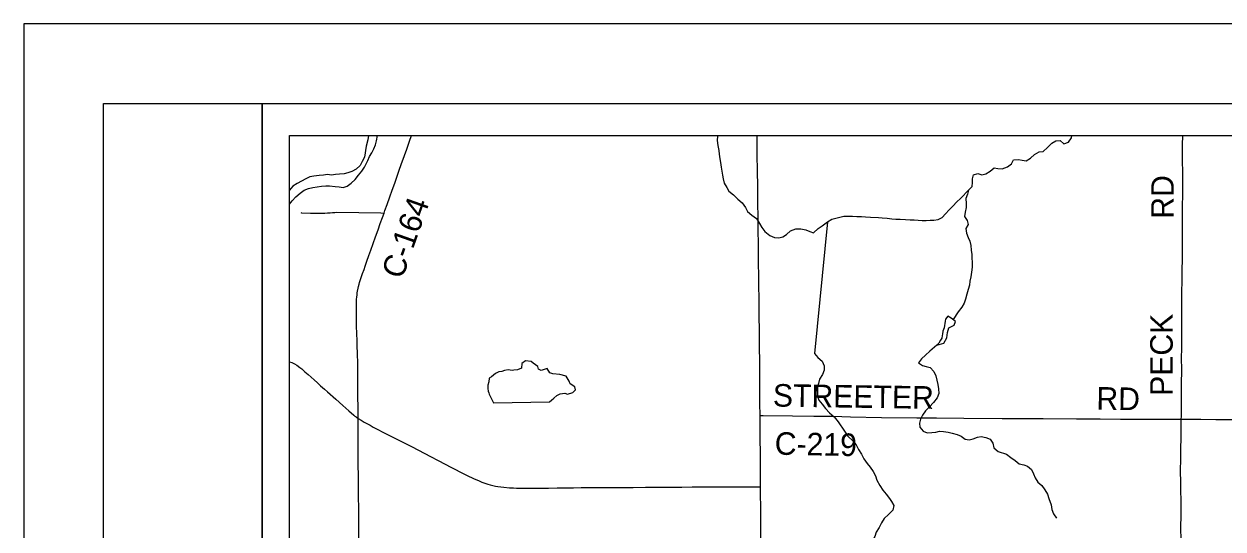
# Model space of a CAD drawing. Extents: x 0 to 34, y 0 to 22.
# Drawn here: x 0 to 7.55, y 18.82 to 22 of the extents above; entities that cross this region are included whole.
import ezdxf

# ---------------------------------------------------------------- set-up
doc = ezdxf.new("R2010")
doc.units = 0
for name, color, linetype in [('GM_X_County_Road', 7, 'Continuous'), ('GM_X_County_Road_Text', 7, 'Continuous'), ('GM_X_Major_River', 7, 'Continuous'), ('GM_X_Minor_Lake', 7, 'Continuous'), ('GM_X_Minor_River', 7, 'Continuous'), ('GM_X_State_Route', 7, 'Continuous'), ('GM_X_Township_Road', 7, 'Continuous'), ('SH_Border', 7, 'Continuous'), ('SH_Cut_Line', 7, 'Continuous'), ('SH_Text', 7, 'Continuous')]:
    doc.layers.add(name, color=color, linetype=linetype)

msp = doc.modelspace()

# ---------------------------------------------------------------- linework, layer by layer
at = {"layer": 'GM_X_County_Road'}
for points in [[(2.2666, 20.8105), (2.2724, 20.8264), (2.2858, 20.8633), (2.3041, 20.9132), (2.3186, 20.9539), (2.3343, 20.9988), (2.3522, 21.0497), (2.3601, 21.0731), (2.3771, 21.122), (2.3869, 21.1504), (2.3946, 21.1718), (2.4095, 21.2132), (2.427, 21.2637), (2.4389, 21.2991)], [(7.286, 19.5135), (7.2862, 19.5297), (7.2864, 19.6137), (7.2873, 19.7224), (7.2888, 19.8343), (7.2879, 19.8886), (7.2887, 19.9679), (7.2894, 20.0347), (7.2899, 20.0999), (7.2903, 20.145), (7.2894, 20.191), (7.2887, 20.2313), (7.2896, 20.3121), (7.2908, 20.3835), (7.2914, 20.427), (7.2921, 20.4517), (7.2923, 20.4641), (7.293, 20.5067), (7.2929, 20.5944), (7.2929, 20.619), (7.2932, 20.6546), (7.2933, 20.7079), (7.2933, 20.7508), (7.2942, 20.8094), (7.2942, 20.8523), (7.2946, 20.9271), (7.2955, 20.9978), (7.2959, 21.0576), (7.2942, 21.1503), (7.2944, 21.1921), (7.2935, 21.2264), (7.294, 21.2523), (7.2947, 21.2833), (7.2954, 21.2991)], [(2.1033, 19.5185), (2.1031, 19.567), (2.1029, 19.5985), (2.1027, 19.6438), (2.1024, 19.7134), (2.1023, 19.7491), (2.1022, 19.7835), (2.1019, 19.818), (2.1016, 19.8431), (2.1012, 19.8755), (2.1003, 19.9139), (2.0995, 19.936), (2.0984, 19.9665), (2.0973, 20.0038), (2.0957, 20.0539), (2.0943, 20.0976), (2.0936, 20.13), (2.093, 20.1663), (2.0927, 20.1819), (2.0928, 20.1999), (2.0929, 20.2245), (2.0933, 20.2419), (2.0938, 20.2566), (2.0944, 20.2686), (2.0956, 20.2822), (2.097, 20.2948), (2.0986, 20.3074), (2.1007, 20.3196), (2.1041, 20.3369), (2.1069, 20.349), (2.1104, 20.3624), (2.1131, 20.3727), (2.1168, 20.3854), (2.121, 20.398), (2.1253, 20.4113), (2.1317, 20.4296), (2.1408, 20.4557), (2.1482, 20.4769), (2.1588, 20.5071), (2.1715, 20.5435), (2.1835, 20.5772), (2.1983, 20.619), (2.2129, 20.6602), (2.2289, 20.7051), (2.2429, 20.7445), (2.2561, 20.7815), (2.2666, 20.8105)], [(2.1088, 18.767), (2.1076, 18.9038), (2.1071, 18.9571), (2.1065, 19.0215), (2.106, 19.0762), (2.1055, 19.1442), (2.1048, 19.2394), (2.1044, 19.3044), (2.1039, 19.3805), (2.1036, 19.4313), (2.1033, 19.5185)], [(4.6341, 19.5365), (4.6542, 19.5363), (4.8374, 19.5343), (4.9723, 19.5333), (5.0953, 19.5316), (5.2034, 19.5274), (5.3978, 19.5241), (5.6207, 19.5222), (5.7446, 19.522), (5.9176, 19.5198), (6.1577, 19.5182), (6.2756, 19.5175), (6.417, 19.5176), (6.6267, 19.5162), (6.7758, 19.5153), (6.9032, 19.5141), (7.1346, 19.5131), (7.286, 19.5135)], [(7.285, 18.7426), (7.284, 18.8433), (7.2844, 18.8984), (7.2841, 18.9654), (7.2824, 19.1009), (7.2818, 19.2024), (7.2826, 19.2499), (7.2836, 19.3184), (7.2848, 19.4039), (7.286, 19.5135)], [(7.286, 19.5135), (7.3057, 19.5134), (7.4098, 19.5125), (7.5034, 19.5116), (7.6091, 19.5105)]]:
    msp.add_lwpolyline(points, dxfattribs=at)
at = {"layer": 'GM_X_Major_River'}
for points in [[(2.1683, 21.2991), (2.1649, 21.271), (2.1534, 21.2314), (2.1432, 21.1623)], [(2.1444, 21.0987), (2.1652, 21.1412), (2.1755, 21.1659), (2.1906, 21.1898), (2.2018, 21.2155), (2.2131, 21.2393), (2.2196, 21.265), (2.2252, 21.2983), (2.2254, 21.2991)], [(2.1432, 21.1623), (2.1281, 21.1357), (2.1159, 21.11), (2.0923, 21.0862), (2.0649, 21.0727), (2.0394, 21.0631), (2.0148, 21.0573), (1.9873, 21.0543), (1.9617, 21.0523), (1.9361, 21.0493), (1.9115, 21.052), (1.8859, 21.0491), (1.8594, 21.0461), (1.8243, 21.0431), (1.7997, 21.0392), (1.7742, 21.0257), (1.7468, 21.0104), (1.7194, 20.9961), (1.6929, 20.9789), (1.6712, 20.9541), (1.6712, 20.9541)], [(1.9241, 20.981), (1.9583, 20.9773), (1.9848, 20.9756), (2.0104, 20.9719), (2.035, 20.9796), (2.0605, 20.9987), (2.086, 21.0207), (2.1067, 21.0483), (2.1265, 21.073), (2.1444, 21.0987)], [(1.6712, 20.8658), (1.6886, 20.8878), (1.7122, 20.9135), (1.7386, 20.9364), (1.7632, 20.9536), (1.7906, 20.9642), (1.8181, 20.9709), (1.8465, 20.9758), (1.872, 20.9788), (1.8995, 20.9808), (1.9241, 20.981)]]:
    msp.add_lwpolyline(points, dxfattribs=at)
at = {"layer": 'GM_X_Minor_Lake'}
for p, q in [((5.8, 20.1304), (5.7926, 20.0885)), ((2.9291, 19.6702), (2.9568, 19.6162))]:
    msp.add_line(p, q, dxfattribs=at)
for points in [[(5.7926, 20.0885), (5.7851, 20.0676), (5.7833, 20.0486), (5.7815, 20.0391), (5.7787, 20.0229), (5.7693, 20.0096), (5.7599, 19.9924), (5.7461, 19.9796), (5.7912, 19.9907), (5.8109, 20.0259), (5.8146, 20.0583), (5.823, 20.0887), (5.8561, 20.106), (5.8636, 20.1288), (5.8369, 20.1496), (5.817, 20.1618), (5.8019, 20.1437), (5.8, 20.1304)], [(2.9568, 19.6162), (3.3079, 19.6217), (3.3201, 19.6332), (3.3362, 19.6466), (3.3551, 19.6628), (3.375, 19.6734), (3.4053, 19.6774), (3.4224, 19.6708), (3.4556, 19.6814), (3.4726, 19.6976), (3.4687, 19.7176), (3.4383, 19.7355), (3.4325, 19.7526), (3.4124, 19.7838), (3.3735, 19.795), (3.3298, 19.7986), (3.3108, 19.8052), (3.2936, 19.8317), (3.2567, 19.8191), (3.2396, 19.8276), (3.2347, 19.8447), (3.2062, 19.8664), (3.1938, 19.8758), (3.1577, 19.8804), (3.135, 19.8641), (3.1332, 19.8347), (3.1067, 19.8231), (3.0849, 19.8221), (3.0726, 19.8201), (3.0489, 19.8238), (3.0261, 19.8199), (3.0081, 19.8141), (2.9891, 19.8121), (2.9693, 19.8015), (2.9428, 19.7805), (2.9295, 19.7719), (2.9258, 19.749), (2.9212, 19.7281), (2.9203, 19.7062), (2.9214, 19.6901), (2.9262, 19.6797), (2.9291, 19.6702)]]:
    msp.add_lwpolyline(points, dxfattribs=at)
at = {"layer": 'GM_X_Minor_River'}
for points in [[(4.3667, 21.2991), (4.3667, 21.2939), (4.3649, 21.2663), (4.3679, 21.2359), (4.3738, 21.2046), (4.3767, 21.1809), (4.3807, 21.1524), (4.3855, 21.1286), (4.3894, 21.0992), (4.3933, 21.0745), (4.3982, 21.0498), (4.4021, 21.0261), (4.4079, 20.9995), (4.4242, 20.972), (4.4376, 20.9474), (4.4671, 20.9257), (4.4938, 20.8983), (4.5224, 20.8737), (4.5424, 20.8444), (4.5558, 20.8197), (4.5825, 20.7961), (4.611, 20.7763), (4.6311, 20.745), (4.6455, 20.7194), (4.6645, 20.6948), (4.695, 20.6693), (4.7245, 20.6571), (4.752, 20.6544), (4.7767, 20.6612), (4.8013, 20.6746), (4.8258, 20.6975), (4.8599, 20.712), (4.8912, 20.7102), (4.9216, 20.7047), (4.9473, 20.6953), (4.9711, 20.6869), (4.9994, 20.7136), (5.0249, 20.7309), (5.059, 20.7548), (5.0855, 20.7711), (5.112, 20.7788), (5.1357, 20.7837), (5.1613, 20.7905), (5.186, 20.7915), (5.2154, 20.7907), (5.2429, 20.789), (5.2723, 20.7882), (5.2979, 20.7864), (5.3302, 20.7837), (5.3796, 20.7821), (5.4033, 20.7803), (5.4346, 20.7785), (5.4631, 20.7749), (5.4878, 20.7722), (5.5153, 20.7714), (5.5495, 20.7696), (5.5798, 20.7679), (5.6036, 20.767), (5.6292, 20.7653), (5.6548, 20.7626), (5.6804, 20.7636), (5.7042, 20.7647), (5.7288, 20.7667), (5.7563, 20.7707), (5.7809, 20.7822), (5.8017, 20.8061), (5.8244, 20.8299), (5.8489, 20.8548), (5.8716, 20.8796), (5.898, 20.9044), (5.9471, 20.9541), (5.9689, 20.978), (5.9706, 21.0017)], [(5.9706, 21.0017), (5.9705, 21.0264), (5.978, 21.0502), (6.0045, 21.0589), (6.0292, 21.0514), (6.0558, 21.0563), (6.0823, 21.0736), (6.1069, 21.0946), (6.1306, 21.09), (6.1581, 21.0892), (6.1913, 21.1017), (6.2178, 21.1208), (6.23, 21.1456), (6.2603, 21.1467), (6.285, 21.143), (6.3088, 21.1384), (6.3362, 21.1566), (6.3608, 21.1795), (6.392, 21.1958), (6.4167, 21.1978), (6.4431, 21.2236), (6.4705, 21.2504), (6.496, 21.2657), (6.5226, 21.2678), (6.5474, 21.247), (6.5758, 21.2566), (6.5937, 21.2843), (6.5977, 21.2991)], [(5.9471, 20.9541), (5.9406, 20.9284), (5.9294, 20.9017), (5.9323, 20.8704), (5.9306, 20.8447), (5.925, 20.8162), (5.9204, 20.7896), (5.9385, 20.763), (5.9443, 20.7393), (5.9302, 20.7126), (5.9332, 20.6832), (5.9447, 20.6576), (5.9543, 20.6339), (5.9611, 20.6054), (5.964, 20.5779), (5.968, 20.5503), (5.9681, 20.5256), (5.9701, 20.5019), (5.9683, 20.4705), (5.9647, 20.4382), (5.9601, 20.4087), (5.9554, 20.3821), (5.9518, 20.3573), (5.9452, 20.3288), (5.9368, 20.2993), (5.9284, 20.2688), (5.92, 20.2431), (5.904, 20.2184), (5.8804, 20.1897), (5.8491, 20.1402)], [(5.059, 20.7548), (4.9764, 19.9257), (4.9984, 19.9011), (5.0241, 19.8775), (5.0375, 19.8491), (5.0367, 19.8215), (5.0273, 19.7948), (5.0075, 19.7643), (5.0029, 19.7387), (4.9964, 19.7139), (4.9965, 19.6892), (4.9957, 19.6588), (5.0043, 19.6332), (5.0244, 19.6086), (5.0463, 19.5802), (5.0702, 19.5537), (5.1006, 19.5272), (5.1264, 19.497), (5.1646, 19.4382), (5.1875, 19.407), (5.219, 19.3767), (5.2381, 19.3521), (5.2534, 19.3237), (5.2716, 19.2924), (5.2878, 19.264), (5.3088, 19.2356), (5.3279, 19.211), (5.3451, 19.1835), (5.3604, 19.156), (5.3691, 19.1304), (5.3873, 19.0963), (5.4073, 19.066), (5.4274, 19.0414), (5.4484, 19.0149), (5.4608, 18.9959)], [(5.7461, 19.9796), (5.7022, 19.9408), (5.6748, 19.9159), (5.6502, 19.893), (5.6314, 19.8673), (5.6561, 19.8522), (5.6799, 19.8457), (5.7055, 19.8382), (5.7275, 19.8136), (5.7399, 19.7861), (5.7476, 19.7586), (5.7535, 19.731), (5.7583, 19.7054), (5.7585, 19.676), (5.7482, 19.6474), (5.7265, 19.6188), (5.7, 19.592), (5.6764, 19.5653), (5.6576, 19.5396), (5.6434, 19.5129), (5.6379, 19.4891), (5.6399, 19.4634), (5.6609, 19.4379), (5.6865, 19.4266), (5.7159, 19.4287), (5.7396, 19.4326), (5.7633, 19.4375), (5.788, 19.4366), (5.8174, 19.4311), (5.844, 19.4246), (5.8745, 19.4162), (5.9001, 19.4058), (5.9258, 19.387), (5.9505, 19.3842), (5.9751, 19.3901), (6.0026, 19.4007), (6.0263, 19.4036), (6.0558, 19.399), (6.0833, 19.3887), (6.0986, 19.3631), (6.1054, 19.3328), (6.1321, 19.3101), (6.1862, 19.2923), (6.2138, 19.2725), (6.2395, 19.2527), (6.2653, 19.2319), (6.2938, 19.2254), (6.3185, 19.2188), (6.3423, 19.1962), (6.3547, 19.1706), (6.3653, 19.145), (6.3825, 19.1165), (6.4073, 19.0958), (6.4273, 19.0683), (6.4426, 19.0418), (6.4522, 19.0133)], [(5.4608, 18.9959), (5.4768, 18.97), (5.4704, 18.9415), (5.4423, 18.9146), (5.4152, 18.8877), (5.3994, 18.8619), (5.3836, 18.8313), (5.3659, 18.8017), (5.3558, 18.775), (5.341, 18.7501), (5.3318, 18.7243), (5.3207, 18.6995), (5.3216, 18.7014)], [(6.4522, 19.0133), (6.4662, 18.9749), (6.4713, 18.9446), (6.482, 18.9172), (6.5002, 18.8908), (6.5012, 18.8908)]]:
    msp.add_lwpolyline(points, dxfattribs=at)
at = {"layer": 'GM_X_State_Route'}
for points in [[(4.6391, 18.8312), (4.6381, 18.912), (4.6369, 19.0877), (4.6358, 19.247), (4.6349, 19.4428), (4.6341, 19.5365), (4.6334, 19.6122), (4.632, 19.8375), (4.6301, 20.0068), (4.6279, 20.2269), (4.626, 20.3977), (4.6244, 20.5125), (4.6232, 20.6076), (4.6219, 20.708), (4.619, 20.9486), (4.6169, 21.1049), (4.6167, 21.1467), (4.6165, 21.1931), (4.6154, 21.2991)], [(4.6469, 18.031), (4.6466, 18.0638), (4.6464, 18.0924), (4.6457, 18.1692), (4.6456, 18.1825), (4.6447, 18.3425), (4.6441, 18.426), (4.644, 18.4368), (4.6439, 18.4575), (4.641, 18.671), (4.6393, 18.8136), (4.6391, 18.8312)]]:
    msp.add_lwpolyline(points, dxfattribs=at)
at = {"layer": 'GM_X_Township_Road'}
for points in [[(1.7435, 20.8132), (1.7477, 20.8125), (1.8043, 20.8103), (1.8189, 20.8098), (1.8341, 20.8099), (1.8588, 20.8098), (1.8848, 20.8101), (1.8938, 20.8104), (1.9118, 20.8113), (1.927, 20.8124), (1.9421, 20.8137), (1.9572, 20.8149), (1.9686, 20.8156), (2.2463, 20.8109), (2.2666, 20.8105)], [(1.6712, 19.8747), (1.6866, 19.8692), (1.7035, 19.8614), (1.7183, 19.853), (1.7372, 19.8394), (1.7489, 19.8297), (1.7691, 19.8116), (1.7885, 19.794), (1.826, 19.7602), (1.8469, 19.7417), (1.8671, 19.7238), (1.8918, 19.7025), (1.9117, 19.6852), (1.9633, 19.6401), (2.008, 19.5998), (2.0441, 19.5664), (2.076, 19.5389), (2.0832, 19.5331), (2.0904, 19.5278), (2.1033, 19.5185)], [(2.1033, 19.5185), (2.1228, 19.5062), (2.1418, 19.4955), (2.1789, 19.4749), (2.1993, 19.4637), (2.2283, 19.4482), (2.26, 19.4322), (2.306, 19.4087), (2.3683, 19.3769), (2.4428, 19.3389), (2.5593, 19.2778), (2.6067, 19.2529), (2.6907, 19.2092), (2.7115, 19.1984), (2.7479, 19.1801), (2.7858, 19.1617), (2.8352, 19.1387), (2.8613, 19.1274), (2.8825, 19.1181), (2.9011, 19.111), (2.9192, 19.105), (2.9354, 19.1002), (2.9515, 19.096), (2.9676, 19.0925), (2.9826, 19.0897), (3.003, 19.0869), (3.0219, 19.0849), (3.0574, 19.0819), (3.0822, 19.0805), (3.1008, 19.0798), (3.124, 19.0792), (3.154, 19.0789), (3.2329, 19.0795), (3.3014, 19.0804), (3.3566, 19.0811), (3.4209, 19.0819), (3.4592, 19.0823), (3.5073, 19.0828), (3.5704, 19.0832), (3.6437, 19.0835), (3.76, 19.084), (3.8358, 19.0843), (3.9136, 19.0847), (3.9933, 19.0853), (4.0717, 19.0858), (4.1416, 19.0864), (4.2075, 19.0868), (4.2564, 19.0871), (4.324, 19.0874), (4.4029, 19.0879), (4.4751, 19.0881), (4.5416, 19.0881), (4.6369, 19.0877)]]:
    msp.add_lwpolyline(points, dxfattribs=at)
at = {"layer": 'SH_Border'}
for points in [[(0.5, 21.5), (1.5, 21.5), (1.5, 0.5), (0.5, 0.5)], [(1.5, 21.5), (33.5, 21.5), (33.5, 0.5), (1.5, 0.5)]]:
    msp.add_lwpolyline(points, close=True, dxfattribs=at)
at = {"layer": 'SH_Cut_Line'}
msp.add_lwpolyline([(0, 0), (34, 0), (34, 22), (0, 22)], close=True, dxfattribs=at)
at = {"layer": 'SH_Text'}
msp.add_lwpolyline([(1.6712, 21.2991), (18.6712, 21.2991), (18.6712, 4.2991), (1.6712, 4.2991)], close=True, dxfattribs=at)

# ---------------------------------------------------------------- texts
at = {"layer": 'GM_X_County_Road_Text'}
for s, rotation, p in [('RD', 90, (7.2384, 20.7745)), ('C-164', 70.53292, (2.3813, 20.3888)), ('PECK', 90, (7.2321, 19.66)), ('STREETER', 359.17467, (4.714, 19.5929)), ('RD', 359.01855, (6.7503, 19.5741)), ('C-219', 358.92048, (4.7253, 19.2903))]:
    msp.add_text(s, height=0.14205, rotation=rotation, dxfattribs=at).set_placement(p)

doc.saveas('drawing.dxf')
